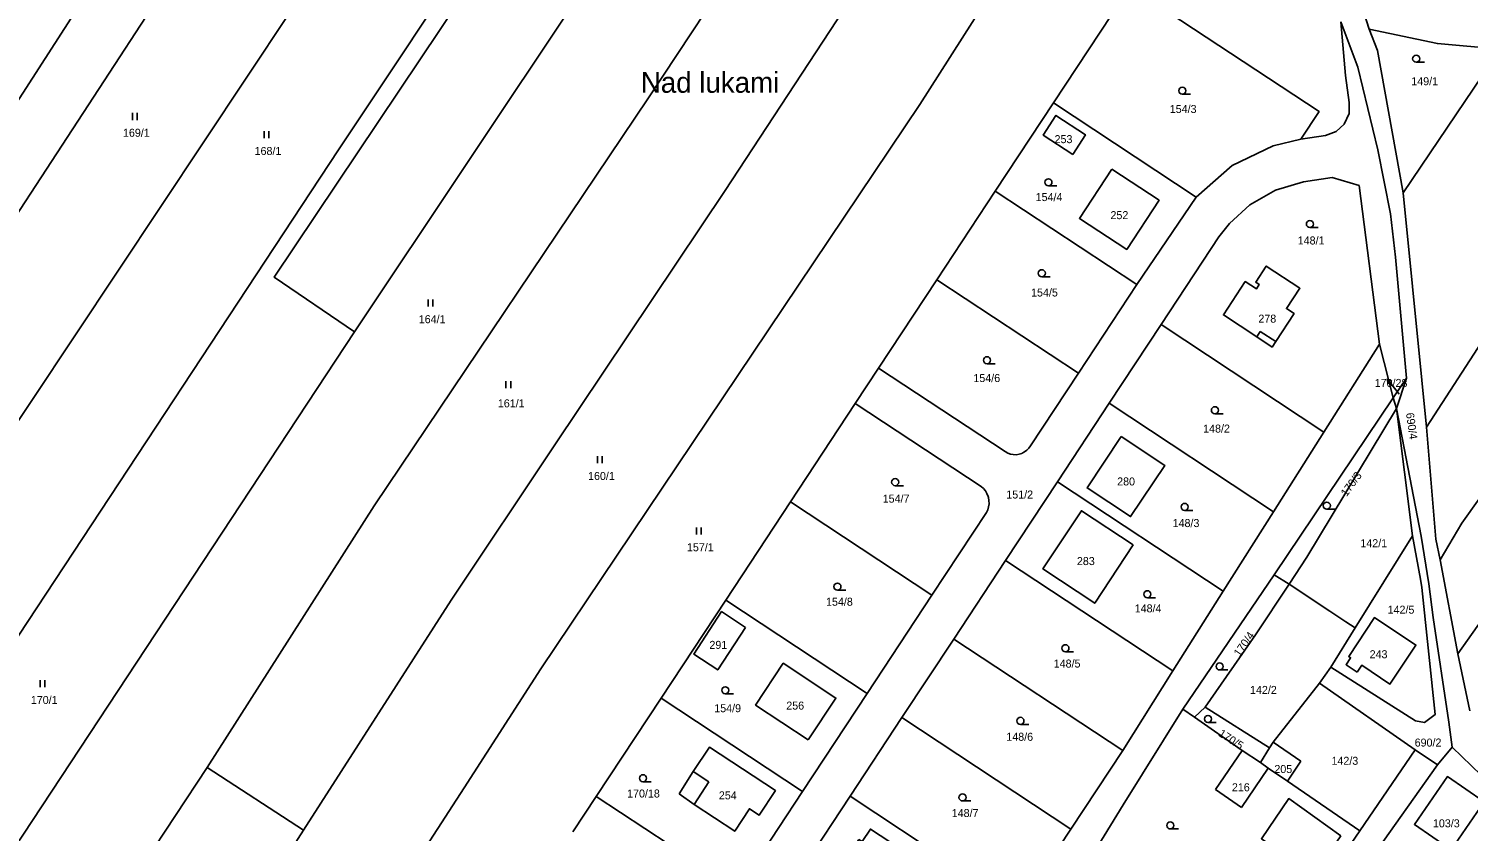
# Model space of a CAD drawing. Extents: x -747333 to -743907, y -1134120 to -1130051.
# Drawn here: x -746642.5 to -746336.6, y -1131796 to -1131625.6 of the extents above; entities that cross this region are included whole.
import ezdxf

# ---------------------------------------------------------------- set-up
doc = ezdxf.new("R2010")
doc.units = 0
for name, color, linetype in [('Hranice parcel', 7, 'Continuous'), ('Parcelní čísla', 7, 'Continuous'), ('Pop  PČ popisy', 7, 'Continuous'), ('Vnitřní kresba', 7, 'Continuous'), ('Značky kultur', 7, 'Continuous')]:
    doc.layers.add(name, color=color, linetype=linetype)

msp = doc.modelspace()

# ---------------------------------------------------------------- linework, layer by layer
at = {"layer": 'Hranice parcel'}
for p, q in [((-746329.82, -1131629.89), (-746350.48, -1131660.43)), ((-746437.14, -1131660.09), (-746424.75, -1131641.3)), ((-746424.75, -1131641.3), (-746394.42, -1131661.31)), ((-746449.53, -1131678.87), (-746437.14, -1131660.09)), ((-746437.14, -1131660.09), (-746407.08, -1131679.91)), ((-746394.42, -1131661.31), (-746407.08, -1131679.91)), ((-746461.91, -1131697.65), (-746449.53, -1131678.87)), ((-746449.53, -1131678.87), (-746419.47, -1131698.69)), ((-746407.08, -1131679.91), (-746419.47, -1131698.69)), ((-746412.92, -1131705.11), (-746401.91, -1131688.42)), ((-746401.91, -1131688.42), (-746367.29, -1131711.24)), ((-746650.27, -1131806.65), (-746573.28, -1131689.92)), ((-746355.48, -1131692.56), (-746367.29, -1131711.24)), ((-746352.57, -1131703.96), (-746355.48, -1131692.56)), ((-746461.91, -1131697.65), (-746466.87, -1131705.17)), ((-746435, -1131715.39), (-746461.91, -1131697.65)), ((-746419.47, -1131698.69), (-746429.65, -1131714.14)), ((-746352.57, -1131703.96), (-746349.77, -1131699.8)), ((-746351.88, -1131706.25), (-746349.77, -1131699.8)), ((-746352.57, -1131703.96), (-746377.87, -1131741.58)), ((-746351.88, -1131706.25), (-746352.57, -1131703.96)), ((-746480.63, -1131726.03), (-746466.87, -1131705.17)), ((-746466.87, -1131705.17), (-746440.15, -1131722.79)), ((-746423.93, -1131721.81), (-746412.92, -1131705.11)), ((-746412.92, -1131705.11), (-746377.99, -1131728.15)), ((-746348.46, -1131733.24), (-746351.88, -1131706.25)), ((-746346.61, -1131733.31), (-746351.88, -1131706.25)), ((-746367.29, -1131711.24), (-746377.99, -1131728.15)), ((-746434.94, -1131738.5), (-746423.93, -1131721.81)), ((-746423.93, -1131721.81), (-746388.68, -1131745.05)), ((-746494.4, -1131746.91), (-746480.63, -1131726.03)), ((-746480.63, -1131726.03), (-746450.58, -1131745.86)), ((-746439.01, -1131728.33), (-746450.58, -1131745.86)), ((-746377.99, -1131728.15), (-746388.68, -1131745.05)), ((-746360.63, -1131752.81), (-746348.46, -1131733.24)), ((-746445.95, -1131755.2), (-746434.94, -1131738.5)), ((-746434.94, -1131738.5), (-746399.37, -1131761.96)), ((-746342.61, -1131738.39), (-746338.81, -1131758.34)), ((-746377.87, -1131741.58), (-746397.28, -1131770.07)), ((-746377.87, -1131741.58), (-746374.71, -1131743.56)), ((-746508.16, -1131767.78), (-746494.4, -1131746.91)), ((-746494.4, -1131746.91), (-746464.34, -1131766.73)), ((-746450.58, -1131745.86), (-746464.34, -1131766.73)), ((-746388.68, -1131745.05), (-746399.37, -1131761.96)), ((-746329.53, -1131745.1), (-746338.81, -1131758.34)), ((-746365.82, -1131761.2), (-746360.63, -1131752.81)), ((-746456.96, -1131771.89), (-746445.95, -1131755.2)), ((-746445.95, -1131755.2), (-746410.06, -1131778.87)), ((-746338.81, -1131758.34), (-746336.31, -1131770.46)), ((-746399.37, -1131761.96), (-746410.06, -1131778.87)), ((-746368.23, -1131764.55), (-746365.82, -1131761.2)), ((-746365.82, -1131761.2), (-746347.81, -1131772.57)), ((-746378.08, -1131777.1), (-746368.23, -1131764.55)), ((-746347.88, -1131778.71), (-746368.23, -1131764.55)), ((-746508.16, -1131767.78), (-746521.93, -1131788.64)), ((-746478.1, -1131787.6), (-746508.16, -1131767.78)), ((-746464.34, -1131766.73), (-746478.1, -1131787.6)), ((-746467.98, -1131788.59), (-746456.96, -1131771.89)), ((-746456.96, -1131771.89), (-746421.07, -1131795.57)), ((-746397.28, -1131770.07), (-746394.81, -1131771.77)), ((-746394.81, -1131771.77), (-746392.55, -1131769.65)), ((-746394.81, -1131771.77), (-746384.65, -1131778.83)), ((-746378.85, -1131778.33), (-746392.55, -1131769.65)), ((-746378.08, -1131777.1), (-746378.85, -1131778.33)), ((-746372.17, -1131781.13), (-746378.08, -1131777.1)), ((-746410.06, -1131778.87), (-746421.07, -1131795.57)), ((-746384.65, -1131778.83), (-746390.3, -1131787.17)), ((-746380.78, -1131781.43), (-746384.65, -1131778.83)), ((-746380.78, -1131781.43), (-746378.85, -1131778.33)), ((-746347.88, -1131778.71), (-746359.64, -1131795.9)), ((-746343.18, -1131781.93), (-746347.88, -1131778.71)), ((-746340.04, -1131778.16), (-746343.18, -1131781.93)), ((-746318.01, -1131799.56), (-746340.04, -1131778.16)), ((-746629.7, -1131820.37), (-746604.57, -1131782.51)), ((-746604.57, -1131782.51), (-746584.14, -1131795.8)), ((-746384.79, -1131790.95), (-746379.11, -1131782.6)), ((-746379.11, -1131782.6), (-746380.78, -1131781.43)), ((-746379.11, -1131782.6), (-746375.03, -1131785.37)), ((-746375.03, -1131785.37), (-746372.17, -1131781.13)), ((-746343.18, -1131781.93), (-746357.15, -1131801.57)), ((-746390.3, -1131787.17), (-746384.79, -1131790.95)), ((-746359.64, -1131795.9), (-746375.03, -1131785.37)), ((-746526.88, -1131796.16), (-746521.93, -1131788.64)), ((-746521.93, -1131788.64), (-746501.28, -1131802.26)), ((-746489.67, -1131805.13), (-746478.1, -1131787.6)), ((-746478.99, -1131805.28), (-746467.98, -1131788.59)), ((-746467.98, -1131788.59), (-746432.08, -1131812.26)), ((-746584.14, -1131795.8), (-746609.27, -1131834.66)), ((-746421.07, -1131795.57), (-746432.08, -1131812.26)), ((-746372.05, -1131814.02), (-746359.64, -1131795.9))]:
    msp.add_line(p, q, dxfattribs=at)
for points in [[(-746542.27, -1131553.07), (-746577.87, -1131608.3), (-746669.36, -1131745.76)], [(-746511.63, -1131551.78), (-746545.3, -1131604.15), (-746576.72, -1131651.31), (-746648.61, -1131760.36)], [(-746573.28, -1131689.92), (-746590.37, -1131678.32), (-746541.73, -1131605.72), (-746507.22, -1131551.86)], [(-746484.27, -1131554.35), (-746525.57, -1131618.34), (-746573.28, -1131689.92)], [(-746575.3, -1131559.78), (-746589.72, -1131580.27), (-746695.71, -1131742.45)], [(-746459.19, -1131562.15), (-746510.85, -1131640.22), (-746569.14, -1131726.93), (-746604.57, -1131782.51)], [(-746597.56, -1131567.52), (-746664.87, -1131671.92), (-746731.85, -1131775.88)], [(-746436.69, -1131571.7), (-746494.56, -1131659.94), (-746530.72, -1131713.92), (-746552.72, -1131746.93), (-746584.14, -1131795.8)], [(-746417.71, -1131586.04), (-746453.14, -1131641.65), (-746533.7, -1131761.53), (-746550, -1131786.81), (-746585.55, -1131841.66)], [(-746365.22, -1131601.11), (-746361.08, -1131615), (-746357.67, -1131625.64)], [(-746424.75, -1131641.3), (-746412.36, -1131622.52), (-746408.5, -1131616.68)], [(-746408.5, -1131616.68), (-746368.33, -1131643.18), (-746372.19, -1131649.02)], [(-746363.69, -1131624.1), (-746362.74, -1131635.52), (-746361.91, -1131641.27), (-746361.94, -1131643.54), (-746362.97, -1131645.86), (-746364.66, -1131647.42), (-746366.95, -1131648.25), (-746372.19, -1131649.02)], [(-746349.77, -1131699.8), (-746352.07, -1131674.11), (-746353.14, -1131664.9), (-746355.82, -1131651.29), (-746360.06, -1131633.75), (-746363.69, -1131624.1)], [(-746357.67, -1131625.64), (-746343.19, -1131628.73), (-746329.82, -1131629.89)], [(-746357.67, -1131625.64), (-746355.93, -1131630.2), (-746350.48, -1131660.43)], [(-746292.81, -1131630.24), (-746318.73, -1131668.93), (-746345.52, -1131710.16)], [(-746342.61, -1131738.39), (-746337.96, -1131730.57), (-746303.62, -1131682.4), (-746277.47, -1131641.33)], [(-746420.66, -1131652.25), (-746426.94, -1131648.17), (-746424.24, -1131643.98), (-746417.96, -1131648.09), (-746420.66, -1131652.25)], [(-746372.19, -1131649.02), (-746378.09, -1131650.44), (-746386.78, -1131654.64), (-746394.42, -1131661.31)], [(-746412.36, -1131655.4), (-746402.32, -1131662), (-746409.2, -1131672.45), (-746419.25, -1131665.85), (-746412.36, -1131655.4)], [(-746401.91, -1131688.42), (-746389.6, -1131669.76), (-746387.39, -1131666.94), (-746383.05, -1131662.99), (-746377.59, -1131659.87), (-746371.64, -1131658.06), (-746365.54, -1131657.14), (-746359.82, -1131658.89), (-746355.48, -1131692.56)], [(-746350.48, -1131660.43), (-746346.47, -1131700.24), (-746345.52, -1131710.16)], [(-746381.56, -1131691.03), (-746388.66, -1131686.34), (-746384, -1131679.26), (-746381.64, -1131680.82), (-746381.03, -1131679.9), (-746381.79, -1131679.4), (-746379.54, -1131675.98), (-746372.41, -1131680.68), (-746375.25, -1131685.01), (-746373.64, -1131686.08), (-746377.54, -1131692.03), (-746378.3, -1131693.2), (-746381.56, -1131691.03)], [(-746374.71, -1131743.56), (-746370.92, -1131737.79), (-746351.88, -1131706.25)], [(-746345.52, -1131710.16), (-746343.55, -1131733.97), (-746342.61, -1131738.39)], [(-746410.37, -1131712.19), (-746401.13, -1131718.31), (-746408.38, -1131729.2), (-746417.63, -1131723.11), (-746410.37, -1131712.19)], [(-746429.65, -1131714.14), (-746429.99, -1131714.646), (-746430.407, -1131715.09), (-746430.892, -1131715.459), (-746431.431, -1131715.745), (-746431.507, -1131715.776), (-746432.089, -1131715.956), (-746432.693, -1131716.039), (-746433.302, -1131716.022), (-746433.9, -1131715.906), (-746434.471, -1131715.693), (-746435, -1131715.39)], [(-746440.15, -1131722.79), (-746439.66, -1131723.227), (-746439.242, -1131723.733), (-746438.906, -1131724.297), (-746438.659, -1131724.906), (-746438.589, -1131725.151), (-746438.476, -1131725.798), (-746438.462, -1131726.454), (-746438.548, -1131727.105), (-746438.732, -1131727.735), (-746439.01, -1131728.33)], [(-746407.8, -1131735.19), (-746415.99, -1131747.58), (-746427, -1131740.3), (-746418.82, -1131727.94), (-746407.8, -1131735.19)], [(-746347.81, -1131772.57), (-746345.9, -1131772.95), (-746343.68, -1131771.24), (-746346.5, -1131744.26), (-746346.78, -1131742.46), (-746348.46, -1131733.24)], [(-746344.07, -1131750.59), (-746345.01, -1131743.5), (-746346.61, -1131733.31)], [(-746392.55, -1131769.65), (-746381.82, -1131754.29), (-746374.71, -1131743.56)], [(-746374.71, -1131743.56), (-746366.06, -1131749.26), (-746362.64, -1131751.54), (-746360.63, -1131752.81)], [(-746490.18, -1131752.73), (-746496.09, -1131761.74), (-746501.19, -1131758.39), (-746495.28, -1131749.37), (-746490.18, -1131752.73)], [(-746360.21, -1131762.23), (-746359.24, -1131760.77), (-746353.28, -1131764.76), (-746347.74, -1131756.47), (-746356.55, -1131750.65), (-746362.01, -1131758.91), (-746361.62, -1131759.17), (-746362.6, -1131760.65), (-746360.21, -1131762.23)], [(-746340.04, -1131778.16), (-746340.74, -1131772.88), (-746344.07, -1131750.59)], [(-746476.87, -1131776.61), (-746488.05, -1131769.22), (-746482.18, -1131760.35), (-746470.99, -1131767.74), (-746476.87, -1131776.61)], [(-746397.28, -1131770.07), (-746409.98, -1131790.4), (-746421.32, -1131808.85)], [(-746504.29, -1131788.08), (-746501.33, -1131783.36), (-746497.88, -1131778.16), (-746483.86, -1131787.38), (-746487.28, -1131792.6), (-746489.36, -1131791.22), (-746492.48, -1131796), (-746501.13, -1131790.31), (-746504.29, -1131788.08)], [(-746363.67, -1131796.98), (-746374.76, -1131789.08), (-746380.59, -1131797.61), (-746371.1, -1131804.04), (-746368.51, -1131800.22), (-746366.72, -1131801.44), (-746363.67, -1131796.98)], [(-746466.13, -1131797.76), (-746465.44, -1131798.22), (-746463.66, -1131795.54), (-746457.45, -1131799.62), (-746463.9, -1131809.41), (-746470.12, -1131805.34), (-746468.34, -1131802.64), (-746469.02, -1131802.17), (-746466.13, -1131797.76)]]:
    msp.add_lwpolyline(points, dxfattribs=at)
at = {"layer": 'Pop  PČ popisy'}
for p, q in [((-746352.04, -1131702.28), (-746353.888, -1131699.915)), ((-746353.888, -1131699.915), (-746352.876, -1131700.396)), ((-746353.888, -1131699.915), (-746353.666, -1131701.013)), ((-746351.32, -1131703.2), (-746352.04, -1131702.28))]:
    msp.add_line(p, q, dxfattribs=at)
at = {"layer": 'Vnitřní kresba'}
for p, q in [((-746381.56, -1131691.03), (-746380.82, -1131689.84)), ((-746380.82, -1131689.84), (-746377.54, -1131692.03)), ((-746501.33, -1131783.36), (-746497.99, -1131785.55)), ((-746497.99, -1131785.55), (-746501.13, -1131790.31))]:
    msp.add_line(p, q, dxfattribs=at)
msp.add_lwpolyline([(-746333.21, -1131789.79), (-746340.23, -1131799.97), (-746348.05, -1131794.58), (-746341.05, -1131784.42), (-746333.21, -1131789.79)], dxfattribs=at)
at = {"layer": 'Značky kultur'}
for p, q in [((-746347.693, -1131632.69), (-746345.943, -1131632.69)), ((-746397.383, -1131639.48), (-746395.633, -1131639.48)), ((-746620.481, -1131644.96), (-746620.481, -1131643.46)), ((-746619.48, -1131644.96), (-746619.48, -1131643.46)), ((-746592.491, -1131648.83), (-746592.491, -1131647.33)), ((-746591.49, -1131648.83), (-746591.49, -1131647.33)), ((-746425.833, -1131658.93), (-746424.083, -1131658.93)), ((-746370.273, -1131667.8), (-746368.523, -1131667.8)), ((-746427.243, -1131678.24), (-746425.493, -1131678.24)), ((-746557.631, -1131684.56), (-746557.631, -1131683.06)), ((-746556.63, -1131684.56), (-746556.63, -1131683.06)), ((-746438.883, -1131696.72), (-746437.133, -1131696.72)), ((-746541.101, -1131701.93), (-746541.101, -1131700.43)), ((-746540.1, -1131701.93), (-746540.1, -1131700.43)), ((-746390.463, -1131707.34), (-746388.713, -1131707.34)), ((-746521.631, -1131717.86), (-746521.631, -1131716.36)), ((-746520.63, -1131717.86), (-746520.63, -1131716.36)), ((-746458.403, -1131722.62), (-746456.653, -1131722.62)), ((-746396.893, -1131727.87), (-746395.143, -1131727.87)), ((-746366.683, -1131727.61), (-746364.933, -1131727.61)), ((-746500.641, -1131733), (-746500.641, -1131731.5)), ((-746499.64, -1131733), (-746499.64, -1131731.5)), ((-746470.663, -1131744.81), (-746468.913, -1131744.81)), ((-746404.803, -1131746.42), (-746403.053, -1131746.42)), ((-746422.223, -1131757.89), (-746420.473, -1131757.89)), ((-746389.463, -1131761.76), (-746387.713, -1131761.76)), ((-746640.071, -1131765.44), (-746640.071, -1131763.94)), ((-746639.07, -1131765.44), (-746639.07, -1131763.94)), ((-746494.503, -1131766.82), (-746492.753, -1131766.82)), ((-746431.783, -1131773.32), (-746430.033, -1131773.32)), ((-746391.923, -1131772.92), (-746390.173, -1131772.92)), ((-746511.993, -1131785.5), (-746510.243, -1131785.5)), ((-746444.093, -1131789.59), (-746442.343, -1131789.59)), ((-746399.943, -1131795.53), (-746398.193, -1131795.53))]:
    msp.add_line(p, q, dxfattribs=at)
for centre in [(-746347.693, -1131631.94), (-746397.383, -1131638.73), (-746425.833, -1131658.18), (-746370.273, -1131667.05), (-746427.243, -1131677.49), (-746438.883, -1131695.97), (-746390.463, -1131706.59), (-746458.403, -1131721.87), (-746396.893, -1131727.12), (-746366.683, -1131726.86), (-746470.663, -1131744.06), (-746404.803, -1131745.67), (-746422.223, -1131757.14), (-746389.463, -1131761.01), (-746494.503, -1131766.07), (-746431.783, -1131772.57), (-746391.923, -1131772.17), (-746511.993, -1131784.75), (-746444.093, -1131788.84), (-746399.943, -1131794.78)]:
    msp.add_circle(centre, 0.75, dxfattribs=at)

# ---------------------------------------------------------------- texts
at = {"layer": 'Parcelní čísla'}
for s, p in [('149/1', (-746348.73, -1131637.57)), ('154/3', (-746400.053, -1131643.46)), ('169/1', (-746622.49, -1131648.51)), ('253', (-746424.534, -1131649.87)), ('168/1', (-746594.52, -1131652.38)), ('154/4', (-746428.553, -1131662.17)), ('252', (-746412.654, -1131666.01)), ('148/1', (-746372.863, -1131671.39)), ('154/5', (-746429.523, -1131682.44)), ('278', (-746381.224, -1131687.99)), ('164/1', (-746559.64, -1131688.11)), ('154/6', (-746441.783, -1131700.61)), ('170/28', (-746356.505, -1131701.65)), ('161/1', (-746542.83, -1131705.98)), ('148/2', (-746392.963, -1131711.34)), ('160/1', (-746523.66, -1131721.41)), ('280', (-746411.234, -1131722.57)), ('154/7', (-746461.053, -1131726.22)), ('151/2', (-746434.783, -1131725.35)), ('148/3', (-746399.443, -1131731.41)), ('157/1', (-746502.65, -1131736.55)), ('142/1', (-746359.55, -1131735.69)), ('283', (-746419.784, -1131739.48)), ('154/8', (-746473.093, -1131748.12)), ('148/4', (-746407.503, -1131749.53)), ('142/5', (-746353.763, -1131749.81)), ('291', (-746497.874, -1131757.28)), ('148/5', (-746424.713, -1131761.25)), ('243', (-746357.584, -1131759.27)), ('142/2', (-746383, -1131766.85)), ('170/1', (-746642.07, -1131768.99)), ('256', (-746481.544, -1131770.18)), ('154/9', (-746496.843, -1131770.73)), ('148/6', (-746434.783, -1131776.8)), ('690/2', (-746348.013, -1131778.03)), ('142/3', (-746365.69, -1131781.9)), ('205', (-746377.824, -1131783.65)), ('170/18', (-746515.365, -1131788.85)), ('216', (-746386.85, -1131787.53)), ('254', (-746495.864, -1131789.24)), ('148/7', (-746446.383, -1131793)), ('103/3', (-746344.13, -1131795.18))]:
    msp.add_text(s, height=1.7, dxfattribs=at).set_placement(p)
for s, rotation, p in [('690/4', 278, (-746349.867, -1131707.241)), ('170/3', 54, (-746362.482, -1131725.069)), ('170/4', 55, (-746385.213, -1131759.067)), ('170/5', 327, (-746389.862, -1131775.662))]:
    msp.add_text(s, height=1.7, rotation=rotation, dxfattribs=at).set_placement(p)
at = {"layer": 'Pop  PČ popisy'}
msp.add_text('Nad lukami', height=4.4, dxfattribs=at).set_placement((-746512.458, -1131639.17))

doc.saveas('drawing.dxf')
